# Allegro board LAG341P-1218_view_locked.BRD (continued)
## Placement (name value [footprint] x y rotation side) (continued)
CV1022  -  [C_0603]  236.26 146.37 0 top
CV1023  -  [C_0603]  247.76 147.27 270 top
CV1024  -  [C_0603]  245.22 152.8 180 top
CV1025  -  [C_0603]  247.26 152.99 270 top
CV1026  -  [C_0603]  233.79 160.83 90 top
CV1027  -  [C_0603]  237.5 160.83 90 top
CV1028  -  [C_0603]  235.03 160.83 90 top
CV1029  -  [C_0603]  236.27 160.83 90 top
CV1030  -  [C_0603]  238.72 160.83 90 top
CV1031  -  [C_0402]  247.38 157.17 90 top
CV1032  -  [C_0402]  242.8 157.14 180 top
CV1033  -  [C_0402]  237.24 153.62 180 top
CV1034  -  [C_0402]  247.45 149.67 90 top
CV1035  -  [C_0402]  243.9 151.66 180 top
CV1036  -  [C_0402]  241.17 154.01 180 top
CV1037  -  [C_0402]  246.24 158.88 90 top
CV1038  -  [C_0402]  234.87 157.76 90 top
CV1039  -  [C_0402]  243.73 154.41 180 top
CV1040  -  [C_0402]  237.3 150.77 180 top
CV1041  -  [C_0402]  242.75 125.04 90 top
CV1042  -  [C_0402]  242.62 134.77 0 top
CV1043  -  [C_0402]  236.85 134.51 180 top
CV1044  -  [C_0402]  244.17 130.25 90 top
CV1045  -  [C_0402]  238.75 122.4 270 top
CV1046  -  [C_0402]  235.01 134.53 180 top
CV1047  -  [C_0402]  242.82 124.19 270 top
CV1048  -  [C_0402]  244.27 132.09 90 top
CV1050  -  [C_0402]  212.66 143.78 180 top
CV1051  -  [C_0402]  217.17 146.31 180 top
CZ4  -  [C_0603]  256.84 105.81 180 top
CZ6  -  [C_0603]  256.84 107.08 180 top
CZ8  -  [C_0603]  257.48 103.27 0 top
CZ9  -  [C_0603]  256.1 110.18 0 top
CZ11  -  [C_0603]  52.5 75.08 0 top
CZ12  -  [C_0603]  259.82 107.9 180 top
CZ18  -  [C_0402]  56.95 72.56 270 top
CZ19  -  [C_0402]  60.52 71.61 0 top
CZ20  -  [C_0402]  53.14 69.97 180 top
CZ26  -  [C_0402]  338.56 126.83 0 bottom
CZ28  -  [C_0402]  178.88 147.91 180 top
CZ29  -  [C_0402]  343.33 126.81 90 bottom
CZ31  -  [C_0402]  342.56 129.62 0 bottom
CZ37  -  [C_0603]  233.22 76.28 270 top
CZ39  -  [C_0603]  272.21 73.68 180 top
CZ41  -  [C_0201]  49.49 96.92 180 top
CZ43  -  [C_0402]  49.33 89.86 90 bottom
CZ44  -  [C_0402]  52.37 95.85 270 bottom
CZ45  -  [C_0402]  234.87 76.29 270 top
CZ46  -  [C_0402]  275.51 77.28 90 top
CZ47  -  [C_0402]  178.99 149.37 180 bottom
CZ49  -  [C_0402]  172.25 133.42 90 top
CZ82  -  [C_0402]  183.95 150.82 90 bottom
CZ86  -  [C_0402]  178.99 151.26 90 bottom
CZ88  -  [C_0402]  178.99 150.31 180 bottom
CZ96  -  [C_0402]  179.57 153.1 90 top
CZ97  -  [C_0402]  178.35 154.01 180 top
CZ98  -  [C_0402]  208.98 114.64 180 top
CZ99  -  [C_0402]  208.62 130.65 90 top
CZ100  -  [C_0201]  12.74 129.11 0 bottom
CZ101  -  [C_0201]  13.64 126.26 90 bottom
CZ104  -  [C_0402]  2.59 82.44 180 bottom
CZ105  -  [C_0402]  120.7 81.93 180 top
CZ106  -  [C_0402]  118.07 80.27 90 top
CZ588  -  [C_0402]  104.88 121.68 0 top
CZ1501  -  [C_0402]  124.11 79.64 180 top
CZ2154  -  [C_0603]  242.48 77.01 180 top
CZ2155  -  [C_0402]  239.4 119.78 180 top
CZ2156  -  [C_0402]  127.3 125.32 270 top
CZ2157  -  [C_0201]  56.44 96.96 270 top
D18  -  [ESD101-B1-02ELS_TSSLP-2-4-2]  341.24 126.57 90 bottom
D74  -  [ESD101-B1-02ELS_TSSLP-2-4-2]  341.11 112.1 270 bottom
D123  -  [ESD8011MUT5G_X3DFN2-2]  324.88 137.24 180 bottom
D124  -  [ESD8011MUT5G_X3DFN2-2]  325.91 137.24 0 bottom
D125  -  [AZ5B25-01F_DFN0603P2Y2]  17.61 164.63 270 bottom
D126  -  [AZ5B25-01F_DFN0603P2Y2]  17.61 165.73 90 bottom
D321  -  [RB751S40T1G_SOD523-2]  174.07 70.57 180 top
D322  -  [AZ5125-01HPR7G_SOD523-2]  279.45 75.23 270 top
D323  -  [ESD8011MUT5G_X3DFN2-2]  318.44 103.94 90 bottom
D324  -  [ESD8011MUT5G_X3DFN2-2]  310.31 101.45 270 bottom
DA2  -  [AZ5123-01FPR7G_DFN1006P2X2]  11.27 119.93 0 bottom
DA3  -  [AZ5123-01FPR7G_DFN1006P2X2]  1.29 111.94 180 bottom
DA4  -  [AZ5123-01FPR7G_DFN1006P2X2]  2.08 112.16 270 top
DA5  -  [AZ5123-01FPR7G_DFN1006P2X2]  2.41 125.79 90 bottom
DA7  -  [AZ5125-01HPR7G_SOD523-2]  11.93 110.85 270 top
DA9  -  [AZ5123-01FPR7G_DFN1006P2X2]  12.72 113.21 270 top
DA14  -  [AZ5125-01HPR7G_SOD523-2]  10.72 110.85 270 top
DA56  -  [RB751S40T1G_SOD523-2]  161.76 179.6 0 top
DA57  -  [RB751S40T1G_SOD523-2]  249.52 113.94 0 top
DE4  -  [PESD5V0U2BT_SOT23-3]  197.79 78.1 180 bottom
DE5  -  [PESD5V0U2BT_SOT23-3]  185.19 80.92 270 top
DE7  -  [RB751S40T1G_SOD523-2]  96.8 101.62 0 top
DE8  -  [RB751S40T1G_SOD523-2]  335.48 114.89 180 bottom
DE9  -  [TVNST52302AB0_SOT523-3]  147.37 74.19 0 bottom
DH1  -  [RB751S40T1G_SOD523-2]  82.65 69.17 180 top
DH2  -  [RB751S40T1G_SOD523-2]  60.21 80.22 180 bottom
DI1  -  [RB751S40T1G_SOD523-2]  346.44 113.21 90 bottom
DI3  -  [AZ5125-02SPR7G_SOT23-3]  345.49 109.34 180 bottom
DI7  -  [AZ1045-04F_DFN2510P10E-10-9]  17.38 168.18 90 top
DI9  -  [AZ1045-04F_DFN2510P10E-10-9]  330.32 140.49 270 top
DI12  -  [BAT54CW-7-F_SOT323-3]  326.57 108.42 0 bottom
DI13  -  [ESD108-B1-CSP0201_WLL-2-1-2]  315.06 99.84 0 bottom
DI14  -  [RB751S40T1G_SOD523-2]  305.51 81.55 180 top
DI15  -  [RB751S40T1G_SOD523-2]  246.2 75.9 180 top
DI16  -  [RB751S40T1G_SOD523-2]  244.5 77.17 0 top
DI17  -  [ESD108-B1-CSP0201_WLL-2-1-2]  314.2 99.84 180 bottom
DL1  -  [AZ5125-02SPR7G_SOT23-3]  342.04 182.14 270 top
DN1  -  [RB751S40T1G_SOD523-2]  324.32 148.8 0 bottom
DN2  -  [RB751S40T1G_SOD523-2]  329.62 144.14 90 bottom
DN3  -  [BAT54CW-7-F_SOT323-3]  333.68 110.07 0 bottom
DT10  -  [PESD24VS2UT_SOT23-3]  11.86 137.62 0 bottom
DT12  -  [ESD108-B1-CSP0201_WLL-2-1-2]  8.94 135.97 90 top
DT13  -  [ESD108-B1-CSP0201_WLL-2-1-2]  8.94 135.27 270 top
DT14  -  [ESD108-B1-CSP0201_WLL-2-1-2]  7.7 134.02 0 top
DT15  -  [ESD108-B1-CSP0201_WLL-2-1-2]  8.94 133.75 90 top
DT16  -  [ESD108-B1-CSP0201_WLL-2-1-2]  8.94 133.05 270 top
DT17  -  [ESD108-B1-CSP0201_WLL-2-1-2]  7.74 131.82 0 top
DT18  -  [ESD108-B1-CSP0201_WLL-2-1-2]  8.94 131.06 90 top
DT19  -  [ESD108-B1-CSP0201_WLL-2-1-2]  8.94 130.38 270 top
DT20  -  [ESD108-B1-CSP0201_WLL-2-1-2]  7.16 137.88 90 bottom
DT21  -  [ESD108-B1-CSP0201_WLL-2-1-2]  7.16 137.18 270 bottom
DT22  -  [ESD108-B1-CSP0201_WLL-2-1-2]  2.29 139.21 90 top
DT23  -  [ESD108-B1-CSP0201_WLL-2-1-2]  5.37 140.3 90 top
DT24  -  [ESD108-B1-CSP0201_WLL-2-1-2]  5.38 139.63 270 top
DT25  -  [ESD108-B1-CSP0201_WLL-2-1-2]  5.51 126.76 90 top
DT26  -  [ESD108-B1-CSP0201_WLL-2-1-2]  7.86 129.05 0 bottom
DT27  -  [ESD108-B1-CSP0201_WLL-2-1-2]  7.16 129.05 180 bottom
DT28  -  [RB751S40T1G_SOD523-2]  6.15 133.34 90 bottom
DT29  -  [RB751S40T1G_SOD523-2]  26.7 116.39 0 top
DT174  -  [BZT52C15LP-7_DFN1006-2]  9.38 137.39 90 bottom
DT175  -  [AZ5B25-01F_DFN0603P2Y2]  13.51 155.28 90 top
DT176  -  [AZ5B25-01F_DFN0603P2Y2]  13.51 154.51 270 top
DT177  -  [AZ5B25-01F_DFN0603P2Y2]  12.62 153.63 90 top
DT178  -  [AZ5B25-01F_DFN0603P2Y2]  12.62 152.86 270 top
DT179  -  [AZ5B25-01F_DFN0603P2Y2]  12.62 150.07 90 top
DT180  -  [AZ5B25-01F_DFN0603P2Y2]  12.62 149.31 270 top
DT181  -  [AZ5B25-01F_DFN0603P2Y2]  13.51 151.72 90 top
DT182  -  [AZ5B25-01F_DFN0603P2Y2]  13.51 150.96 270 top
DV1  -  [BAT54CW-7-F_SOT323-3]  45.77 93.93 180 bottom
DV2  -  [BAT54CW-7-F_SOT323-3]  43.23 93.93 180 bottom
DV7  -  [BAT54CW-7-F_SOT323-3]  63.55 95.33 180 top
DV12  -  [IP4220CZ6_SC-74-6]  56.36 96.72 270 bottom
DV13  -  [BAT54CW-7-F_SOT323-3]  206.87 112.86 90 top
DV14  -  [RB751S40T1G_SOD523-2]  211.89 109.59 90 top
DV15  -  [RB751S40T1G_SOD523-2]  213.16 119.3 270 top
DV16  -  [BAT54CW-7-F_SOT323-3]  247.8 110.89 0 top
DZ59  -  [RB751S40T1G_SOD523-2]  126.92 127.99 270 top
FD1  -  [FIDUCIAL_C40M80]  340.98 74.19 0 top
FD2  -  [FIDUCIAL_C40M80]  22.4 176.01 0 top
FD3  -  [FIDUCIAL_C40M80]  21.2 176.87 180 bottom
FD4  -  [FIDUCIAL_C40M80]  340.58 74.19 180 bottom
FD5  -  [FIDUCIAL_C40M80]  219.13 164.74 180 bottom
FD6  -  [FIDUCIAL_C40M80]  130.73 176.68 0 top
H1  -  [H_2P3]  246.16 68.79 0 top
H2  -  [H_2P3]  26.76 172.69 0 top
H5  -  [H_3P9]  245.81 140.69 0 top
H9  -  [H_2P5]  246.46 186.59 0 top
H10  -  [H_2P5]  1.76 71.19 0 top
H11  -  [H_2P1N]  4.91 69.24 0 top
H12  -  [H_6P0N]  6.86 95.89 0 top
H16  -  [H_3P9]  183.55 156.96 0 top
H17  -  [H_2P1X2P5N]  25.37 177.03 346 top
H23  -  [EMIST_SUL-12A2M_1P]  100.56 127.84 270 bottom
H24  -  [EMIST_SUL-12A2M_1P]  100.56 152.94 270 bottom
H25  -  [EMIST_SUL-12A2M_1P]  110.76 121.74 180 bottom
H37  -  [H_3P2]  12.46 69.61 0 top
H38  -  [H_3P2]  2.51 87.83 0 top
H39  -  [H_2P5]  118.76 185.69 0 top
H40  -  [H_2P5]  345.76 70.19 0 top
H41  -  [H_2P8]  206.06 71.71 0 top
H42  -  [H_2P8]  141.46 71.71 0 top
H43  -  [H_2P3]  324.09 143.14 0 top
H45  -  [H_3P9]  183.55 123.52 180 top
H46  -  [H_3P9]  117.36 133.64 0 top
H47  -  [H_6P0N]  340.66 95.89 0 top
H48  -  [H_4P1]  341.76 80.49 0 top
H49  -  [H_2P3]  340.96 187.19 0 top
H50  -  [CLIP_C6-PM]  335.52 184.64 180 bottom
H54  -  [CLIP_C5P5-NPM]  257.35 106.44 180 bottom
H55  -  [CLIP_C5P5-NPM]  73.01 100.58 180 bottom
H59  -  [H_2P9X2P1N]  345.76 73.99 0 top
JAPS  -  [ACES_50506-01841-P01_18P]  176.39 74.63 180 bottom
JAUDIO  -  [ACES_88028-3010M_30P]  1.76 84.34 0 top
JCR  -  [T-SOL_156-1051902601_19P-T]  328.01 123.24 90 top
JDEG1  -  [ACES_50521-01041-P01_10P]  310.78 98.57 180 bottom
JDIMM1  -  [BELLW_SD-80886-1021_260P-T]  105.14 94.54 180 bottom
JDIMM2  -  [BELLW_SD-80886-1021_260P-T]  181.44 94.54 180 bottom
JEDP1  -  [ACES_59003-04006-001_40P]  65.49 103.22 0 bottom
JFAN1  -  [ACES_50224-00401-001_4P]  92.36 102.42 0 bottom
JFAN2  -  [ACES_50224-00401-001_4P]  334.96 121.39 90 bottom
JFP  -  [ACES_50521-00841-P01_8P-T]  315.86 102.28 0 bottom
JHDD  -  [J-L_UCNR2234B020-0_20P]  229.12 77.68 0 bottom
JHDMI1  -  [ACON_HMRB9-AK120C_19P]  9.53 146.62 270 top
JHP1  -  [YUQIU_PJ567-F07J1BE-C_6P]  8.56 123.56 90 top
JKB  -  [E-T_6710K-Y15M-31L_15P]  161.06 77.59 180 bottom
JLPDE1  -  [ACES_50521-01041-P01_10P]  297.32 98.57 180 bottom
JNGFF1  -  [CONCR_213AAAA32FA_67P]  326.32 151.12 0 bottom
JNGFF2  -  [CONCR_213MAAA32FA_67P-T]  258.24 89.74 270 bottom
JRTC  -  [E-T_3806K-F02N-03R_2P]  327.51 171.54 0 top
JSPI1  -  [ACES_50521-01041-P01_10P]  113.33 73.3 180 bottom
JTAG1  -  [SHORTPADS]  300.79 92.73 0 bottom
JTP  -  [ACES_51524-0080N-001_8P]  190.76 77.99 180 bottom
JTS  -  [ACES_50208-00601-P01_6P]  348.12 124.64 90 bottom
JTS1  -  [ACES_50208-00801-003_8P]  343.71 114.95 0 bottom
JUSB1  -  [TAIWI_USB019-107CRL-TWD_10P-T]  12.45 173.89 270 top
JUSB2  -  [TAIWI_USB019-107CRL-TWD_10P-T]  335.08 136.64 90 top
JUSBC1  -  [JAE_DX07S024XJ2_24P-T]  5.62 135.75 270 top
JXDP  -  [SAMTE_BSH-030-01-L-D-A_60P]  125.96 152.7 90 top
LA1  -  [MURAT_BLM15PX600SN1D_2P]  10.1 103.52 0 top
LA2  -  [MURAT_BLM21PG600SN1D_L0805_2P]  12.05 106.58 90 top
LA3  -  [MURAT_BLM15PX600SN1D_2P]  12.88 106.61 270 bottom
LA4  -  [MURAT_BLM15BB220SN1D_2P]  2.3 93.45 0 bottom
LA5  -  [MURAT_BLM15AX700SN1D_2P]  6.61 125.81 180 bottom
LA6  -  [MURAT_BLM15AX700SN1D_2P]  12.13 118.1 90 bottom
LA7  -  [MURAT_BLM15AX700SN1D_2P]  12.73 115.1 270 top
LA8  -  [MURAT_BLM15AX700SN1D_2P]  4.75 112.17 180 top
LED1  -  [LED_LTW-270TLA_2P]  346.76 175.28 270 top
LED2  -  [LED_LTW-270TLA_2P]  346.76 171.68 270 top
LED3  -  [LED_LTW-270TLA_2P]  346.76 168.08 270 top
LED4  -  [LED_LTW-270TLA_2P]  346.76 164.48 270 top
LED5  -  [LED_LTW-270TLA_2P]  346.76 160.88 270 top
LED6  -  [LED_HT-F196BP5_2P]  332.97 186.94 180 top
LH1  -  [MURAT_BLM15PX221SN1D_2P]  89.71 74.08 0 top
LH2  -  [MURAT_BLM15PX221SN1D_2P]  99.45 90.32 90 top
LH3  -  [MURAT_BLM15PX221SN1D_2P]  69.82 91.97 90 bottom
LH4  -  [MURAT_BLM15PX221SN1D_2P]  100.59 89.29 180 bottom
LI1  -  [INPAQ_MCM1012B900F06BP_4P]  341.56 109.5 0 bottom
LI2  -  [INPAQ_MCM1012B900F06BP_4P]  325.86 134.56 90 bottom
LI5  -  [INPAQ_MCM1012B900F06BP_4P]  18.6 167.27 270 bottom
LM1  -  [CHILI_PBY160808T-300Y-N_2P]  24.69 144.05 270 bottom
LM2  -  [CHILI_PBY160808T-300Y-N_2P]  18.72 135.15 90 bottom
LM3  -  [CHILI_PBY160808T-300Y-N_2P]  16.55 143.15 0 bottom
LM4  -  [CHILI_PBY160808T-300Y-N_2P]  22.51 135.37 0 bottom
LM5  -  [CHILI_PBY160808T-300Y-N_2P]  16.04 136.8 0 bottom
LN1  -  [INPAQ_MCM1012B900F06BP_4P]  327.52 147.79 90 bottom
LT1  -  [MAG_MLV-YT10NR68N-M1L_2P]  20.99 115.84 180 bottom
LT12  -  [CHILI_CMMI21T-900Y-N_4P]  11.7 133.2 90 top
LT13  -  [CHILI_CMMI21T-900Y-N_4P]  8.18 139.55 90 top
LT14  -  [CHILI_PBY160808T-300Y-N_2P]  14.61 107.91 90 bottom
LV22  -  [INPAQ_MCM1012B900F06BP_4P]  56.16 92.18 90 bottom
LV23  -  [CHILI_PBY160808T-300Y-N_2P]  196.77 121.48 90 bottom
LV24  -  [KC_FBMA-L11-160808300LMA25T_2P]  189.15 151.92 90 top
MD3  -  [ESD108-B1-CSP0201_WLL-2-1-2]  317.49 100.09 0 bottom
MD4  -  [ESD108-B1-CSP0201_WLL-2-1-2]  319.01 100.09 180 bottom
ML17  -  [CHILI_CMMI21T-900Y-N_4P]  315.05 96.96 180 bottom
NOREF  -  []  198.82 81.55 0 top
NOREF#2  -  []  151.97 98.67 0 top
NOREF#3  -  []  245.81 140.69 0 top
NOREF#4  -  []  206.66 0 0 top
NOREF#5  -  []  183.55 156.96 0 top
NOREF#6  -  []  138.38 24.5 0 top
NOREF#7  -  []  117.36 133.64 0 top
NOREF#8  -  []  183.55 123.52 0 top
NOREF#9  -  []  66.04 137.46 180 bottom
NOREF#10  -  []  216.26 72.9 90 bottom
NOREF#11  -  []  81.25 78.51 180 bottom
NOREF#12  -  []  231.95 102.13 90 bottom
NOREF#13  -  []  204.14 101.62 90 bottom
NOREF#14  -  []  146.22 113.3 180 bottom
PC106  -  [C_0402]  23.71 156.72 0 bottom
PC107  -  [C_0402]  23.67 86.76 90 bottom
PC108  -  [C_0402]  24.56 86.76 90 bottom
PC109  -  [C_0402]  25.12 82.31 0 top
PC110  -  [C_0402]  25.12 83.2 0 top
PC114  -  [C_0402]  25.21 147.69 0 bottom
PC115  -  [C_0402]  25.21 148.71 0 bottom
PC200  -  [C_0402]  22.64 70.47 270 top
PC201  -  [C_0603]  14.15 96.28 180 bottom
PC202  -  [C_0603]  8.31 84.98 180 bottom
PC203  -  [C_0805]  10.97 93.24 90 top
PC204  -  [C_0402]  14.02 101.49 180 bottom
PC205  -  [C_0402]  29.96 70.44 270 top
PC206  -  [C_0402]  29.96 71.39 90 top
PC207  -  [C_0402]  29.33 68.57 0 top
PC208  -  [C_0402]  28.37 92.22 180 top
PC209  -  [C_0402]  26.72 95.01 0 bottom
PC210  -  [C_0402]  19.66 95.01 0 top
PC211  -  [C_0603]  20.82 90.95 180 top
PC212  -  [C_0402]  17.58 87.83 90 top
PC213  -  [C_0402]  22.53 85.24 90 top
PC214  -  [C_0402]  23.8 75.01 270 top
PC215  -  [C_0402]  25.4 76.52 90 top
PC216  -  [C_0402]  22.66 72.28 270 top
PC217  -  [C_0402]  17.63 94.25 0 top
PC218  -  [C_0201]  75.1 96.26 135 top
PC219  -  [C_0402]  59.75 81.43 180 bottom
PC220  -  [C_0603]  64.05 91.88 315 top
PC221  -  [C_0201]  69 89.42 135 top
PC222  -  [C_0402]  67.5 89.62 135 top
PC223  -  [C_0402]  71.12 97.32 315 top
PC335  -  [C_0603]  345.81 92.6 90 top
PC400  -  [C_0603]  345.72 88.11 0 top
PC401  -  [C_0402]  346.65 90.06 180 bottom
PC402  -  [C_0402]  345.67 87.01 0 bottom
PC403  -  [C_0402]  322.54 87.32 90 top
PC404  -  [C_0402]  323.43 87.32 90 top
PC405  -  [C_0402]  321.65 87.32 90 top
PC406  -  [C_0603]  326.49 87.26 90 top
PC407  -  [C_0402]  319.74 87.32 90 top
PC408  -  [C_0402]  320.76 87.32 90 top
PC409  -  [C_0603]  324.76 87.26 90 top
PC410  -  [C_0603]  337.62 91.27 0 top
PC411  -  [C_0603]  342 84.41 0 top
PC412  -  [C_B2]  325.52 93.22 90 top
PC413  -  [C_B2]  321.96 71.34 270 top
PC414  -  [C_0603]  330.63 99.46 180 top
PC415  -  [C_0402]  335.9 88.68 270 top
PC416  -  [C_0402]  330.12 85.67 90 top
PC417  -  [C_0603]  337.21 83.67 90 top
PC418  -  [C_0402]  338.34 88.17 180 top
PC419  -  [C_0603]  338.58 87.03 180 top
PC420  -  [C_D]  321.23 82.95 270 top
PC456  -  [C_B2]  318.76 71.34 270 top
PC500  -  [C_0402]  134.75 75.6 270 top
PC501  -  [C_0402]  134.75 75.6 270 bottom
PC502  -  [C_0201]  128.45 76.4 180 bottom
PC503  -  [C_0603]  136 75.71 0 bottom
PC504  -  [C_0603]  124.32 69.49 180 bottom
PC505  -  [C_0201]  130.1 69.72 0 top
PC506  -  [C_0402]  130.96 69.64 90 bottom
PC507  -  [C_0805]  119.68 71.1 270 bottom
PC508  -  [C_0805]  119.68 71.1 270 top
PC509  -  [C_0805]  121.46 71.1 270 bottom
PC510  -  [C_0805]  121.46 71.1 270 top
PC511  -  [C_0402]  132.46 70.72 270 bottom
PC512  -  [C_0402]  130.01 70.58 270 bottom
PC513  -  [C_0603]  136 75.71 0 top
PC600  -  [C_0603]  282.31 94.57 180 bottom
PC601  -  [C_0603]  273.79 97.3 270 bottom
PC602  -  [C_0603]  274.05 98.09 270 top
PC603  -  [C_0402]  272.72 96.74 270 top
PC604  -  [C_0402]  272.72 96.92 270 bottom
PC605  -  [C_0603]  282.12 97.94 90 top
PC606  -  [C_0603]  279.65 98.04 180 top
PC607  -  [C_0603]  285.1 92.6 0 bottom
PC608  -  [C_D1]  256.02 95.07 90 bottom
PC609  -  [C_0402]  286.05 99.84 180 bottom
PC610  -  [C_0603]  287.9 93.87 270 bottom
PC611  -  [C_0603]  262.56 94.63 270 bottom
PC612  -  [C_0402]  289.48 98.38 90 bottom
PC613  -  [C_0402]  289.6 96.41 0 top
PC614  -  [C_0402]  289.6 97.43 0 bottom
PC615  -  [C_0603]  273.99 99.21 90 bottom
PC700  -  [C_0402]  200.65 183.57 90 top
PC701  -  [C_0402]  194.68 181.84 90 bottom
PC702  -  [C_0603]  199.59 183.18 90 top
PC703  -  [C_0603]  193.56 181.62 90 bottom
PC704  -  [C_0402]  192.79 178.71 180 top
PC705  -  [C_0402]  192.79 179.6 180 top
PC706  -  [C_0402]  189.53 180.56 270 top
PC707  -  [C_0402]  190.49 187.42 270 top
PC708  -  [C_0603]  196.75 182.09 90 top
PC709  -  [C_0402]  204.95 187.34 0 top
PC710  -  [C_0402]  194.68 185.11 90 top
PC711  -  [C_0402]  191.44 186.5 90 top
PC712  -  [C_0402]  185.27 187.47 0 top
PC713  -  [C_0402]  188.34 185.57 180 top
PC714  -  [C_0402]  186.49 184.73 90 top
PC715  -  [C_0402]  212.17 181.86 270 bottom
PC716  -  [C_0402]  211.28 181.86 270 bottom
PC717  -  [C_0805]  213.63 181.93 270 bottom
PC718  -  [C_B2]  212.29 184.15 270 bottom
PC719  -  [C_0805]  208.58 184.84 90 top
PC721  -  [C_0805]  210.93 182.03 270 top
PC722  -  [C_0805]  210.36 184.84 90 top
PC723  -  [C_0603]  214.58 185.4 90 bottom
PC724  -  [C_0603]  211.89 185.5 90 top
PC725  -  [C_0402]  182.68 184.41 180 top
PC800  -  [C_0402]  104.88 131.84 0 bottom
PC801  -  [C_0402]  105.51 135.02 0 top
PC802  -  [C_0603]  104.38 132.99 0 top
PC803  -  [C_0603]  104.38 132.99 0 bottom
PC804  -  [C_0402]  102.03 126.97 270 bottom
PC805  -  [C_0402]  108.76 126.69 90 top
PC806  -  [C_0402]  109.65 130.88 90 bottom
PC807  -  [C_0603]  111.05 126.83 90 bottom
PC808  -  [C_0603]  111.05 126.83 90 top
PC809  -  [C_0603]  112.71 126.83 90 top
PC810  -  [C_0402]  103.56 129.35 90 bottom
PC900  -  [C_0402]  240.08 184.55 90 bottom
PC901  -  [C_0402]  240.97 184.55 90 bottom
PC902  -  [C_0201]  236.14 183.19 270 top
PC903  -  [C_0603]  244.14 183.03 270 bottom
PC904  -  [C_0603]  234.49 181.56 90 top
PC905  -  [C_0402]  236.4 180.03 90 bottom
PC906  -  [C_0402]  239.06 177.74 90 top
PC907  -  [C_0805]  227.25 184.08 90 bottom
PC908  -  [C_0805]  225.54 184.08 90 bottom
PC909  -  [C_0805]  225.56 184.08 90 top
PC910  -  [C_0805]  227.27 184.07 90 top
PC911  -  [C_0402]  242.14 178.66 270 bottom
PC912  -  [C_0402]  238.18 178.66 270 bottom
PC913  -  [C_0603]  242.49 182.9 270 bottom
PC1000  -  [C_0805]  162.85 171.54 90 bottom
PC1001  -  [C_0805]  164.92 169.83 270 top
PC1003  -  [C_0402]  154.33 198.16 180 bottom
PC1004  -  [C_0402]  163.39 169.25 270 top
PC1005  -  [C_0402]  166.55 185.27 90 bottom
PC1006  -  [C_0603]  205.22 138.57 90 top
PC1007  -  [C_0603]  207.19 142.32 90 top
PC1008  -  [C_0603]  209.24 138.6 0 top
PC1009  -  [C_0603]  206.04 144.8 180 top
PC1010  -  [C_0603]  204.01 134.62 270 top
PC1011  -  [C_0603]  204.98 135.6 90 top
PC1012  -  [C_0603]  201.85 144.77 0 top
PC1013  -  [C_0603]  204.44 128.61 0 top
PC1014  -  [C_0603]  201.85 137.88 0 top
PC1015  -  [C_0402]  164.06 181.69 0 top
PC1016  -  [C_0603]  204.56 131.01 0 top
PC1017  -  [C_0402]  165.66 185.27 90 bottom
PC1018  -  [C_0402]  162.45 186.06 180 bottom
PC1019  -  [C_B2]  182.95 161.88 0 bottom
PC1020  -  [C_B2]  188.55 161.84 0 bottom
PC1021  -  [C_B2]  161.01 201.81 90 bottom
PC1022  -  [C_0603]  162.58 176.86 90 bottom
PC1023  -  [C_0603]  201.79 140.1 0 top
PC1024  -  [C_0603]  186.79 194.84 180 top
PC1025  -  [C_0603]  204.33 141.08 0 top
PC1026  -  [C_0603]  204.5 129.81 0 top
PC1027  -  [C_0603]  205.09 142.32 90 top
PC1028  -  [C_0603]  207.31 134.68 270 top
PC1029  -  [C_0603]  208.09 140.89 180 top
PC1030  -  [C_0402]  163.47 176.71 270 bottom
PC1031  -  [C_0402]  211.98 138.16 90 top
PC1032  -  [C_0402]  204.95 132.21 180 top
PC1033  -  [C_0402]  206.6 135.6 0 top
PC1034  -  [C_0402]  201.32 134.66 180 top
PC1035  -  [C_0402]  208.83 133.35 270 top
PC1036  -  [C_0402]  211.96 134.92 0 top
PC1037  -  [C_0402]  210.61 133.35 270 top
PC1038  -  [C_0402]  213.48 141.36 0 top
PC1039  -  [C_0402]  202.54 135.91 0 top
PC1040  -  [C_0402]  211.61 133.35 270 top
PC1041  -  [C_0402]  169.08 186.11 270 bottom
PC1042  -  [C_0805]  163.4 167.16 270 bottom
PC1043  -  [C_0805]  165.35 176.99 0 top
PC1045  -  [C_0402]  154.32 197.25 180 bottom
PC1046  -  [C_0402]  163.65 171.5 180 top
PC1047  -  [C_0603]  167.17 181.64 90 top
PC1048  -  [C_0603]  182.59 164.51 90 top
PC1049  -  [C_0402]  202.55 121.56 180 bottom
PC1050  -  [C_0402]  202.55 122.83 180 bottom
PC1051  -  [C_0603]  183.85 164.5 90 top
PC1052  -  [C_0603]  185.11 164.5 90 top
PC1053  -  [C_0603]  206.17 132.2 0 top
PC1054  -  [C_0402]  168.74 183.96 270 bottom
PC1055  -  [C_0402]  169.68 182.3 0 bottom
PC1056  -  [C_0603]  171.15 183.2 270 top
PC1057  -  [C_0603]  179.31 195.29 180 top
PC1058  -  [C_0603]  182.59 168.47 0 top
PC1059  -  [C_0603]  179.31 191.36 180 top
PC1060  -  [C_0603]  182.59 169.69 0 top
PC1061  -  [C_0603]  179.31 193.96 180 top
PC1062  -  [C_0603]  179.31 192.63 180 top
PC1063  -  [C_0603]  182.59 170.9 0 top
PC1064  -  [C_0603]  179.31 200.49 180 top
PC1065  -  [C_0603]  179.31 201.83 180 top
PC1066  -  [C_0603]  179.31 196.63 180 top
PC1067  -  [C_0603]  179.31 203.09 180 top
PC1068  -  [C_0603]  179.31 204.31 180 top
PC1069  -  [C_0603]  179.31 197.9 180 top
PC1070  -  [C_0603]  179.31 199.2 180 top
PC1100  -  [C_0402]  116.2 167.53 180 top
PC1101  -  [C_0402]  112.9 168.67 180 top
PC1102  -  [C_0402]  109.65 168.24 270 top
PC1103  -  [C_0402]  117.14 168.37 270 top
PC1104  -  [C_0402]  112.88 170.45 0 top
PC1105  -  [C_0402]  112.9 169.56 180 top
PC1106  -  [C_0402]  110.77 173.18 270 bottom
PC1107  -  [C_0402]  112.55 173.18 270 bottom
PC1108  -  [C_0402]  116.2 170.2 180 top
PC1109  -  [C_0402]  115.19 170.74 180 bottom
PC1110  -  [C_0402]  114.27 172.56 270 bottom
PC1111  -  [C_0402]  116.38 172.05 270 top
PC1112  -  [C_0402]  115.48 171.95 90 top
PC1113  -  [C_0402]  105.28 172.74 180 bottom
PC1114  -  [C_0402]  105.28 173.63 180 bottom
PC1115  -  [C_0402]  116.76 174.85 270 top
PC1116  -  [C_0402]  119 172.87 180 top
PC1117  -  [C_0402]  119.68 175.48 270 top
PC1118  -  [C_0402]  104.32 172.03 90 top
PC1119  -  [C_0402]  105.21 174.57 90 top
PC1120  -  [C_0402]  113.64 173.88 0 bottom
PC1121  -  [C_0402]  103.35 175.41 0 top
PC1122  -  [C_0402]  106.53 176.17 0 bottom
PC1123  -  [C_0402]  115.62 178.66 270 top
PC1124  -  [C_0402]  117.4 176.47 90 top
PC1125  -  [C_0402]  116.51 177.39 270 top
PC1126  -  [C_0402]  105.21 177.11 90 top
PC1127  -  [C_0402]  104.32 177.11 90 top
PC1128  -  [C_0402]  106.05 178.96 180 top
PC1129  -  [C_0402]  115.62 180.43 270 top
PC1130  -  [C_0402]  113.59 182.21 270 top
PC1131  -  [C_0402]  106.05 185.18 180 top
PC1132  -  [C_0603]  112.45 181.44 90 top
PC1133  -  [C_0402]  115.62 179.39 90 bottom
PC1134  -  [C_0402]  105.13 179.88 0 top
PC1135  -  [C_0402]  113.26 180.36 0 bottom
PC1136  -  [C_0402]  114.55 178.2 180 bottom
PC1137  -  [C_0402]  105.13 182.64 0 top
PC1202  -  [C_D]  166.24 170.73 90 bottom
PC1203  -  [C_0805]  136.45 184.13 270 bottom
PC1204  -  [C_0805]  134.42 184.13 270 top
PC1205  -  [C_0402]  125.78 180.92 90 top
PC1206  -  [C_0402]  123.75 180.92 90 top
PC1207  -  [C_0402]  124.76 180.92 90 top
PC1208  -  [C_0603]  128.26 186.2 0 bottom
PC1209  -  [C_0402]  135.12 182.38 90 bottom
PC1210  -  [C_0603]  133.08 186.2 0 bottom
PC1211  -  [C_B3]  127.05 176.65 270 top
PC1214  -  [C_B3]  123.75 176.65 270 top
PC1216  -  [C_0603]  129.21 183.47 269.8 top
PC1217  -  [C_0603]  134.04 177.25 90 top
PC1222  -  [C_0402]  144.07 182.38 90 bottom
PC1223  -  [C_0805]  143.56 184.13 270 top
PC1224  -  [C_0805]  136.19 184.13 270 top
PC1225  -  [C_0402]  126.8 180.92 90 top
PC1226  -  [C_0402]  131.75 183.74 270 top
PC1227  -  [C_0603]  140.51 187.41 270 bottom
PC1228  -  [C_0603]  143.05 187.41 270 bottom
PC1229  -  [C_0603]  138.35 183.47 270 top
PC1230  -  [C_0603]  141.66 177.25 90 top
PC1231  -  [C_0805]  145.34 184.13 270 top
PC1232  -  [C_0805]  145.4 184.13 270 bottom
PC1233  -  [C_0402]  140.13 183.86 270 top
PC1234  -  [C_0402]  141.02 183.86 270 top
PC1251  -  [C_0402]  148.7 184.05 270 top
PC1252  -  [C_0402]  153.09 184.05 270 top
PC1254  -  [C_0805]  150.04 184.51 270 top
PC1256  -  [C_0805]  151.75 184.51 270 top
PC1257  -  [C_0603]  148.64 187.28 270 bottom
PC1258  -  [C_0402]  152.96 182.19 90 bottom
PC1259  -  [C_0603]  151.31 187.22 270 bottom
PC1260  -  [C_0603]  147.24 183.47 270 top
PC1261  -  [C_0603]  149.28 177.25 90 top
PC1262  -  [C_0402]  159.75 183.93 270 top
PC1263  -  [C_0402]  160.64 183.93 270 top
PC1264  -  [C_0805]  158.36 184.51 270 top
PC1265  -  [C_0805]  156.64 184.51 270 top
PC1268  -  [C_0603]  156.13 187.28 270 bottom
PC1269  -  [C_0402]  160.45 182.95 90 bottom
PC1270  -  [C_0603]  158.74 187.22 270 bottom
PC1271  -  [C_0603]  154.61 183.34 270 top
PC1272  -  [C_0603]  156.26 177.25 90 top
PC1501  -  [C_0402]  183.14 183.44 180 bottom
PC1502  -  [C_0603]  202.82 134.62 270 top
PC1503  -  [C_0603]  208.84 134.77 0 top
PC1504  -  [C_0402]  201.55 136.48 180 top
PC1505  -  [C_0805]  198.83 194.98 0 bottom
PC1507  -  [C_0603]  209.33 143.21 0 top
PC1508  -  [C_0402]  210.55 136.47 90 top
PC1509  -  [C_0805]  198.83 193.2 0 bottom
PC1510  -  [C_0402]  193.68 174.9 180 top
PC1511  -  [C_0402]  193.68 175.79 180 top
PC1512  -  [C_0603]  206.81 138.07 0 top
PC1513  -  [C_0603]  210.62 141.94 180 top
PC1514  -  [C_0603]  203.31 143.08 180 top
PC1515  -  [C_0402]  206.67 139.49 0 top
PC1516  -  [C_0402]  202.03 141.75 0 top
PC1517  -  [C_0402]  182.01 181.58 270 bottom
PC1518  -  [C_0402]  183.14 182.55 180 bottom
PC1519  -  [C_0603]  189.88 180.29 90 bottom
PC1520  -  [C_0402]  190.3 184.12 270 bottom
PC1521  -  [C_0603]  186.3 171.02 90 top
PC1522  -  [C_0402]  180.49 185.72 0 bottom
PC1523  -  [C_0603]  191.69 169.54 180 top
PC1524  -  [C_0603]  191.69 170.74 180 top
PC1525  -  [C_0603]  191.69 168.29 180 top
PC1526  -  [C_0603]  195.69 171.6 0 top
PC1527  -  [C_0603]  193.98 172.14 90 top
PC1528  -  [C_0603]  191.57 171.91 90 top
PC1529  -  [C_B2]  169.36 196.54 0 bottom
PC1530  -  [C_B2]  192.11 161.87 180 bottom
PC1531  -  [C_0402]  184.1 185.83 0 bottom
PC1532  -  [C_0402]  185.92 185.81 90 bottom
PC1600  -  [C_0402]  242.49 175.53 270 bottom
PC1601  -  [C_0201]  240.06 169.87 180 bottom
PC1602  -  [C_0603]  244.02 175.52 180 top
PC1603  -  [C_0402]  243.85 174.44 180 top
PC1604  -  [C_0603]  239.06 164.29 270 bottom
PC1605  -  [C_0402]  244.73 168.17 180 bottom
PC1606  -  [C_0402]  246.56 168.11 90 bottom
PC1607  -  [C_0603]  245.48 163.49 0 bottom
PC1608  -  [C_0603]  245.48 166.01 0 bottom
PC1609  -  [C_0603]  245.48 164.74 0 bottom
PC1610  -  [C_0603]  245.48 162.27 0 bottom
PC1611  -  [C_0402]  246.61 172.99 0 bottom
PC1612  -  [C_0402]  245.67 168.62 270 bottom
PC1613  -  [C_0603]  243.64 175.9 270 bottom
PC1700  -  [C_0805]  105.5 136.92 0 top
PC1701  -  [C_0402]  103.38 138.07 180 bottom
PC1702  -  [C_0402]  103.38 137.18 180 bottom
PC1703  -  [C_0805]  105.5 138.7 0 top
PC1704  -  [C_0402]  102.46 138.96 0 bottom
PC1705  -  [C_0603]  109.91 134.45 90 bottom
PC1706  -  [C_0603]  107.37 134.45 90 bottom
PC1707  -  [C_0603]  111.49 137.81 0 bottom
PC1708  -  [C_0603]  108.95 143.78 180 top
PC1709  -  [C_0402]  110.41 160.11 270 top
PC1710  -  [C_0402]  111.3 160.11 270 bottom
PC1711  -  [C_0805]  111.81 161.02 270 top
PC1712  -  [C_0805]  109.11 161.31 180 top
PC1713  -  [C_0603]  105.46 165.31 270 bottom
PC1714  -  [C_0402]  110.41 159.2 90 bottom
PC1715  -  [C_0603]  108 165.31 270 bottom
PC1716  -  [C_0603]  102.67 160.99 270 bottom
PC1717  -  [C_0603]  104.64 155.47 0 top
PC1800  -  [C_0402]  176.58 76.98 90 top
PC1801  -  [C_0603]  178.27 77.45 90 bottom
PC1802  -  [C_0402]  178.5 83.29 180 top
PC1803  -  [C_0603]  181.38 81.73 270 top
PC1804  -  [C_0402]  180.95 77.96 90 top
PC1900  -  [C_0603]  52.88 75.33 90 bottom
PC1901  -  [C_0603]  51.61 75.33 90 bottom
PC1902  -  [C_0603]  48.63 69.11 0 top
PC1903  -  [C_0603]  49.07 75.33 90 bottom
PC1904  -  [C_0603]  47.8 75.33 90 bottom
PC1905  -  [C_0603]  48.65 71.64 0 top
PC1906  -  [C_0603]  48.63 70.38 0 top
PC1907  -  [C_0603]  50.34 75.33 90 bottom
PC1908  -  [C_0603]  48.63 68.6 0 bottom
PC1909  -  [C_D]  166.89 166.49 270 bottom
PC1910  -  [C_0402]  46.38 76.9 180 top
PC1911  -  [C_0402]  46.34 76.01 270 top
PC1912  -  [C_0402]  45.45 76.01 270 top
PC1913  -  [C_0603]  41.83 75.39 90 top
PC1914  -  [C_0603]  31.55 94.51 90 bottom
PC1915  -  [C_0603]  32.82 94.51 90 bottom
PC1916  -  [C_0603]  32.82 94.51 90 top
PC1917  -  [C_0603]  34.09 94.51 90 bottom
PC1918  -  [C_0603]  35.36 94.51 90 bottom
PC1919  -  [C_0603]  34.09 94.51 90 top
PC1920  -  [C_0603]  31.55 94.51 90 top
PC1921  -  [C_0603]  30.28 94.51 90 top
PC1922  -  [C_0603]  30.28 94.51 90 bottom
PC1923  -  [C_0402]  41.58 90.9 270 bottom
PC1924  -  [C_0402]  41.58 88.21 90 bottom
PC1925  -  [C_0402]  51.28 80.23 270 bottom
PC1926  -  [C_0603]  50.22 78.89 90 top
PC1927  -  [C_0402]  39.47 76.85 0 top
PC1928  -  [C_0402]  51.73 81.55 0 top
PC1929  -  [C_0603]  41.26 79.14 180 top
PC1930  -  [C_0603]  24.77 90.37 270 bottom
PC1931  -  [C_0603]  26.21 92.6 0 bottom
PC1932  -  [C_0402]  29.13 83.79 270 bottom
PC1933  -  [C_0402]  40.44 86.12 180 top
PC1934  -  [C_0402]  50.52 86.44 0 top
PC1935  -  [C_0402]  40.13 81.55 180 top
PC1936  -  [C_0402]  36.25 73.42 0 top
PC1937  -  [C_0402]  31.1 79.72 270 top
PC1938  -  [C_0402]  40.13 82.57 180 top
PC1939  -  [C_0402]  45.59 87.25 90 top
PC1940  -  [C_0402]  43.04 87.19 90 top
PC1941  -  [C_0402]  46.52 87.25 90 top
PC1942  -  [C_0402]  41.07 84.3 270 top
PC1943  -  [C_0402]  40.13 85.11 180 top
PC1944  -  [C_0402]  60.45 83.14 180 top
PC1945  -  [C_0402]  39.54 87.08 0 top
PC2000  -  [C_0603]  180.01 192.13 90 bottom
PC2001  -  [C_D2E]  149.94 165.12 180 bottom
PC2002  -  [C_D2E]  154.33 165.12 0 bottom
PC2003  -  [C_0603]  145.72 171.66 90 top
PC2004  -  [C_0201]  153.98 139.92 0 top
PC2005  -  [C_0201]  160.5 153.57 0 top
PC2006  -  [C_0201]  152.62 145.56 180 top
PC2007  -  [C_0201]  158.95 136.31 180 top
PC2008  -  [C_0201]  165.52 136.28 0 top
PC2009  -  [C_0201]  153.05 147.88 180 top
PC2010  -  [C_0603]  156.95 155.2 270 top
PC2011  -  [C_EEFSS0D221R]  159.17 143.92 0 top
PC2012  -  [C_0603]  159.01 147.15 180 top
PC2013  -  [C_0603]  154.77 151.48 0 top
PC2014  -  [C_0603]  155.05 140.9 0 top
PC2015  -  [C_0603]  158.56 149.65 180 top
PC2016  -  [C_0603]  163.93 147.18 180 top
PC2017  -  [C_0603]  164.36 137.88 180 top
PC2018  -  [C_0603]  159.54 137.88 180 top
PC2019  -  [C_D2E]  198.11 169.01 270 bottom
PC2020  -  [C_B2]  119.56 145.03 90 bottom
PC2021  -  [C_0603]  143.58 137.32 180 top
PC2022  -  [C_0603]  119.81 142.32 270 top
PC2023  -  [C_0603]  144.47 144.93 0 top
PC2024  -  [C_0603]  143.52 144.89 180 top
PC2025  -  [C_0603]  149.47 146.52 0 top
PC2026  -  [C_0603]  149.45 147.77 0 top
PC2027  -  [C_0603]  149.18 143.26 0 top
PC2028  -  [C_EEFSS0D221R]  149.94 166.13 180 top
PC2029  -  [C_0201]  155.69 152.44 0 top
PC2030  -  [C_0201]  160.57 148.07 0 top
PC2031  -  [C_0201]  153.99 138.7 0 top
PC2032  -  [C_0201]  160.85 136.94 0 top
PC2033  -  [C_0201]  165.56 136.91 0 top
PC2034  -  [C_0201]  153.97 138.12 0 top
PC2035  -  [C_0201]  163.72 136.92 180 top
PC2036  -  [C_0201]  158.92 136.98 180 top
PC2037  -  [C_0201]  163.5 148.07 180 top
PC2038  -  [C_0201]  159.04 150.61 180 top
PC2039  -  [C_0603]  159.4 140.82 180 top
PC2040  -  [C_0603]  160.13 164.36 0 top
PC2041  -  [C_0603]  156.36 144.38 90 top
PC2042  -  [C_0201]  160.52 153 0 top
PC2043  -  [C_0201]  165.62 154.7 0 top
PC2044  -  [C_0201]  153.98 136.23 0 top
PC2045  -  [C_0201]  155.69 153.69 180 top
PC2046  -  [C_0201]  155.35 148.18 0 top
PC2047  -  [C_0201]  165.46 151.6 0 top
PC2048  -  [C_0201]  163.69 150.89 180 top
PC2049  -  [C_0201]  163.33 151.79 180 top
PC2050  -  [C_0201]  152.62 138.45 180 top
PC2051  -  [C_0201]  159.69 150.5 0 top
PC2052  -  [C_0201]  155.69 153.03 0 top
PC2053  -  [C_0201]  158.68 148.66 180 top
PC2054  -  [C_0201]  165.47 150.89 0 top
PC2055  -  [C_0201]  160.49 151.78 0 top
PC2056  -  [C_0201]  153.98 139.33 0 top
PC2057  -  [C_0201]  165.37 152.42 0 top
PC2058  -  [C_0201]  165.37 153.56 0 top
PC2059  -  [C_0201]  163.32 152.94 180 top
PC2060  -  [C_0201]  163.33 153.54 180 top
PC2061  -  [C_0201]  165.62 155.34 0 top
PC2062  -  [C_0201]  158.7 148.07 180 top
PC2063  -  [C_0201]  165.37 148.07 0 top
PC2064  -  [C_0201]  160.5 152.39 0 top
PC2065  -  [C_0201]  154.02 137.47 0 top
PC2066  -  [C_0201]  159.68 151.08 0 top
PC2067  -  [C_0201]  163.73 136.28 180 top
PC2068  -  [C_0201]  152.62 140.29 180 top
PC2069  -  [C_0201]  152.62 144.16 180 top
PC2070  -  [C_0201]  154 136.85 0 top
PC2071  -  [C_0201]  160.84 136.36 0 top
PC2072  -  [C_0201]  163.34 152.36 180 top
PC2073  -  [C_0201]  165.37 152.99 0 top
PC2074  -  [C_0201]  149.84 152.51 0 top
PC2075  -  [C_0201]  143.09 136.42 180 top
PC2076  -  [C_0201]  149.78 136.43 0 top
PC2077  -  [C_0201]  149.77 151.2 0 top
PC2078  -  [C_0201]  149.71 149.95 0 top
PC2079  -  [C_0201]  149.35 154.56 0 top
PC2080  -  [C_0201]  143.01 135.43 270 top
PC2081  -  [C_0201]  143.95 135.37 270 top
PC2082  -  [C_0201]  150.98 136.43 0 top
PC2083  -  [C_0201]  141.91 135.82 90 top
PC2084  -  [C_0201]  144.82 135.39 270 top
PC2085  -  [C_0201]  150.72 135.6 0 top
PC2086  -  [C_0603]  160.13 165.56 0 top
PC2087  -  [C_0603]  155.15 143.37 270 top
PC2088  -  [C_0603]  160.13 166.77 0 top
PC2089  -  [C_0603]  160.16 149.61 0 top
PC2090  -  [C_0603]  146.99 171.66 90 top
PC2091  -  [C_0603]  144.64 146.52 0 top
PC2092  -  [C_0603]  144.35 143.24 0 top
PC2093  -  [C_0603]  149.55 140.26 0 top
PC2094  -  [C_0603]  144.62 147.77 0 top
PC2095  -  [C_0603]  152.7 171.66 90 top
PC2096  -  [C_0603]  160.12 147.18 0 top
PC2097  -  [C_0603]  165.38 137.88 0 top
PC2098  -  [C_0603]  164.95 147.18 0 top
PC2099  -  [C_0603]  151.43 171.66 90 top
PC2100  -  [C_0603]  160.13 167.98 0 top
PC2101  -  [C_0603]  160.55 137.88 0 top
PC2102  -  [C_0603]  144.45 171.67 90 top
PC2103  -  [C_0603]  164.92 149.6 0 top
PC2104  -  [C_0603]  165.37 139.13 0 top
PC2105  -  [C_0603]  163.95 149.59 180 top
PC2106  -  [C_0603]  160.55 139.11 0 top
PC2107  -  [C_0603]  159.6 139.12 180 top
PC2108  -  [C_0603]  165.18 140.77 0 top
PC2109  -  [C_0603]  164.23 140.82 180 top
PC2110  -  [C_0603]  160.42 140.82 0 top
PC2111  -  [C_0603]  164.35 139.11 180 top
PC2112  -  [C_0603]  156.42 143.37 270 top
PC2113  -  [C_0603]  154.79 147.25 0 top
PC2114  -  [C_0603]  136.45 171.66 90 top
PC2115  -  [C_0603]  154.8 149.67 0 top
PC2116  -  [C_0603]  152.9 141.88 180 top
PC2117  -  [C_0603]  155.09 144.38 90 top
PC2118  -  [C_0603]  116.51 142.32 270 top
PC2119  -  [C_0603]  115.24 142.32 270 top
PC2120  -  [C_0603]  113.97 142.32 270 top
PC2121  -  [C_0603]  148.53 137.32 180 top
PC2122  -  [C_0603]  144.72 137.32 0 top
PC2123  -  [C_0603]  149.23 144.91 0 top
PC2124  -  [C_0603]  148.22 144.91 180 top
PC2125  -  [C_0603]  149.55 137.32 0 top
PC2126  -  [C_0603]  149.51 138.99 0 top
PC2127  -  [C_0603]  148.5 138.99 180 top
PC2128  -  [C_0603]  144.69 138.99 0 top
PC2129  -  [C_0603]  143.54 138.99 180 top
PC2130  -  [C_0603]  148.4 140.26 180 top
PC2131  -  [C_0603]  148.45 146.52 180 top
PC2132  -  [C_0603]  148.43 147.77 180 top
PC2133  -  [C_0603]  148.17 143.26 180 top
PC2134  -  [C_0603]  144.59 140.26 0 top
PC2135  -  [C_0603]  143.45 140.26 180 top
PC2136  -  [C_0603]  143.33 143.24 180 top
PC2137  -  [C_0603]  143.62 146.52 180 top
PC2138  -  [C_0603]  143.61 147.77 180 top
PC2139  -  [C_0603]  169.34 142.84 180 top
PC2140  -  [C_0603]  169.34 141.62 180 top
PC2141  -  [C_0603]  169.34 144.04 180 top
PC2142  -  [C_0603]  169.34 145.31 180 top
PC2143  -  [C_0603]  169.43 140.38 180 top
PC2144  -  [C_0603]  117.02 155.28 90 top
PC2145  -  [C_0603]  115.75 155.28 90 top
PC2146  -  [C_0603]  114.48 155.28 90 bottom
PC2147  -  [C_0603]  117.02 155.28 90 bottom
PC2148  -  [C_0603]  115.75 155.28 90 bottom
PC2149  -  [C_0603]  114.48 155.28 90 top
PC2150  -  [C_0603]  173.69 159.02 90 bottom
PC2151  -  [C_0603]  176.25 192.13 90 bottom
PC2152  -  [C_0603]  177.52 192.13 90 bottom
PC2153  -  [C_0603]  178.79 192.13 90 bottom
PD100  -  [AZ5125-01HPR7G_SOD523-2]  26.09 148.75 90 top
PD101  -  [TVNST52302AB0_SOT523-3]  11.86 76.92 0 top
PD102  -  [TVNST52302AB0_SOT523-3]  19.1 69.8 180 top
PD200  -  [PDS1040-13_POWERDI5-3]  13 86.76 90 bottom
PD201  -  [PDS1040-13_POWERDI5-3]  18.01 86.76 90 bottom
PD202  -  [RB751V-40_SOD323-2]  19.54 77.36 180 top
PD203  -  [RB520SM-30T2R_EMD2-2]  64.73 89.23 225 top
PD204  -  [RB520SM-30T2R_EMD2-2]  62.59 92.03 225 top
PD1900  -  [RB751V-40_SOD323-2]  55.42 82.62 270 top
PD1902  -  [RB751V-40_SOD323-2]  57.55 82.62 270 top
PD1903  -  [BAT54CW_SOT323-3]  60.26 78.68 0 top
PD1904  -  [SMF22A-SOD123FL-2-S]  55.78 73.29 270 bottom
PH1100  -  [R_0402]  103.63 150.89 180 bottom
PH1101  -  [R_0402]  131.11 173.68 90 bottom
PH1102  -  [R_0402]  110.59 151.4 0 bottom
PH1103  -  [R_0402]  127.94 180.54 90 bottom
PH1104  -  [R_0402]  106.35 134.94 90 bottom
PJP200  -  [JUMP_43X118]  23.63 94.62 180 top
PJP400  -  [JUMP_43X118]  316.34 78 0 top
PJP402  -  [JUMP_43X118]  322.47 92.02 180 top
PJP403  -  [JUMP_43X118]  315.78 72.41 180 top
PJP500  -  [JUMP_43X118]  118.59 73.73 90 bottom
PJP600  -  [JUMP_43X118]  277.35 97.97 180 bottom
PJP601  -  [JUMP_43X39]  280.91 97.62 0 bottom
PJP602  -  [JUMP_43X79]  280.78 96.09 270 top
PJP603  -  [JUMP_43X118]  254.5 92.39 270 bottom
PJP701  -  [JUMP_43X118]  216.7 184.83 0 bottom
PJP702  -  [JUMP_43X118]  214 184.93 0 top
PJP801  -  [JUMP_43X118]  113.04 125.37 0 bottom
PJP900  -  [JUMP_43X39]  222.4 182.9 0 bottom
PJP1302  -  [JUMP_43X79]  112.98 78.58 180 bottom
PJP1303  -  [JUMP_43X79]  116.26 79.22 90 bottom
PJP1600  -  [JUMP_43X118]  242.37 164.02 270 bottom
PJP1604  -  [JUMP_43X79]  161.85 117.92 270 top
PL104  -  [MURAT_BLM15AG102SN1D_2P]  24.16 149.13 90 top
PL105  -  [TAI-T_HCB2012KF-121T50_2P]  23.83 153.51 0 bottom
PL106  -  [TAI-T_HCB2012KF-121T50_2P]  23.83 155.33 0 bottom
PL107  -  [TAI-T_HCB2012KF-121T50_2P]  27.76 83.36 180 bottom
PL108  -  [TAI-T_HCB2012KF-121T50_2P]  24.31 85.67 270 bottom
PL200  -  [TAI-T_HCB2012KF-121T50_2P]  28.63 94.63 180 top
PL201  -  [TAI-T_HCB2012KF-121T50_2P]  28.63 96.41 180 top
PL400  -  [CYNTE_PCMB063T-3R3MS_2P]  329.07 95.21 0 top
PL401  -  [CYNTE_PCMB103T-2R2MS_2P]  335.58 74.14 180 top
PL402  -  [TAI-T_HCB2012KF-121T50_2P]  316.09 81.62 0 top
PL403  -  [TAI-T_HCB2012KF-121T50_2P]  316.09 83.4 0 top
PL500  -  [TAI-T_HCB2012KF-121T50_2P]  136.32 79.01 270 bottom
PL501  -  [CYNTE_PCMB053T-1R0MS_2P]  127.45 73.18 180 bottom
PL600  -  [CYNTE_PCMB063T-1R0MS_2P]  260.3 98.95 0 bottom
PL601  -  [TAI-T_HCB2012KF-121T50_2P]  277.35 94.43 180 bottom
PL700  -  [L_7X7X3_M_2P]  202.41 182.92 0 bottom
PL777  -  [TAI-T_HCB2012KF-121T50_2P]  194.49 179.94 270 top
PL800  -  [CYNTE_PCMB053T-1R0MS_2P]  104.05 125.24 0 bottom
PL801  -  [TAI-T_HCB2012KF-121T50_2P]  102.7 134.64 0 top
PL900  -  [TAI-T_HCB2012KF-121T50_2P]  245.67 180.1 90 bottom
PL901  -  [CYNTE_PCMB053T-1R0MS_2P]  233.38 181.66 180 bottom
PL1000  -  [TAI-T_HCB2012KF-121T50_2P]  162 173.47 0 top
PL1001  -  [TAI-T_HCB2012KF-121T50_2P]  162.01 175.28 0 top
PL1002  -  [MAG_MMD-06DZIR22MEM2L_2P]  177.44 167.06 0 bottom
PL1003  -  [MAG_MMD-06DZIR22MEM2L_2P]  178.04 174.12 0 bottom
PL1200  -  [TAI-T_HCB2012KF-121T50_2P]  127.18 174.17 90 bottom
PL1201  -  [TAI-T_HCB2012KF-121T50_2P]  125.27 174.17 90 bottom
PL1202  -  [L_7X7X4_M]  135.31 177.29 270 bottom
PL1203  -  [L_7X7X4_M]  142.93 176.91 270 bottom
PL1204  -  [TAI-T_HCB2012KF-121T50_2P]  123.37 174.17 90 bottom
PL1251  -  [L_7X7X4_M]  150.55 176.91 270 bottom
PL1252  -  [L_7X7X4_M]  158.17 176.91 270 bottom
PL1500  -  [MAG_MMD-06DZIR22MEM2L_2P]  187.7 167.02 0 bottom
PL1501  -  [TAI-T_HCB2012KF-121T50_2P]  195 177.02 270 top
PL1502  -  [TAI-T_HCB2012KF-121T50_2P]  196.77 177.02 270 top
PL1600  -  [TAI-T_HCB2012KF-121T50_2P]  245.36 178.86 270 bottom
PL1601  -  [L_2P5X2X1P2_F_2P]  241.99 168.08 270 bottom
PL1700  -  [TAI-T_HCB2012KF-121T50_2P]  104.95 134.42 90 bottom
PL1701  -  [TAI-T_HCB2012KF-121T50_2P]  103.05 134.42 90 bottom
PL1702  -  [L_7X7X4_M]  104.98 146.96 0 bottom
PL1703  -  [TAI-T_HCB2012KF-121T50_2P]  112.15 161.69 180 bottom
PL1704  -  [MAG_MMD05CZR47M_4P]  105.06 153.94 0 bottom
PL1900  -  [MAGLA_MMD-05CZ-1R0M-M7L_2P]  48.9 72.09 0 bottom
PL1901  -  [MAG_MMD-10DZ-1R0M-X1A_2P]  34.09 71.47 90 bottom
PQ100  -  [FDV301N-G_SOT23-3]  21.26 149.47 0 top
PQ101  -  [MMBT3904WH_SOT323-3]  22.28 154.41 180 top
PQ200  -  [FDMC6679AZ_MLP8-5]  12.04 95.14 0 bottom
PQ201  -  [FDMC6679AZ_MLP8-5]  9.17 87.01 180 bottom
PQ202  -  [AO3409_SOT23-3]  7.67 88.9 180 top
PQ203  -  [DMN65D8LDW-7_SOT363-6]  13.27 89.79 90 top
PQ204  -  [DMN65D8LW-7_SOT323-3]  6.82 91.44 90 top
PQ205  -  [DMN65D8LW-7_SOT323-3]  12.06 98.41 0 bottom
PQ206  -  [DMN65D8LW-7_SOT323-3]  14.72 96.41 270 top
PQ207  -  [FDMC6679AZ_MLP8-5]  21.89 93.36 90 bottom
PQ208  -  [FDMC6679AZ_MLP8-5]  18.95 95.14 270 bottom
PQ209  -  [FDMC6679AZ_MLP8-5]  23.16 88.92 180 bottom
PQ210  -  [AO3409_SOT23-3]  25.07 88.66 0 top
PQ211  -  [AO3409_SOT23-3]  15.06 88.82 180 top
PQ212  -  [DMN65D8LDW-7_SOT363-6]  27.72 87.33 0 top
PQ213  -  [DMN65D8LDW-7_SOT363-6]  15.4 90.71 0 top
PQ214  -  [DMN65D8LDW-7_SOT363-6]  17.05 82.63 0 top
PQ215  -  [DMN65D8LDW-7_SOT363-6]  15.99 96.68 270 top
PQ216  -  [DMN65D8LDW-7_SOT363-6]  18.1 80.6 180 top
PQ217  -  [DMN65D8LW-7_SOT323-3]  20.75 81.13 0 top
PQ219  -  [2N7002KDW_SOT363-6]  75.82 99.66 315 top
PQ220  -  [DMN66D0LDW-7_SOT363-6]  57.15 83.94 270 bottom
PQ221  -  [DMN66D0LDW-7_SOT363-6]  55.58 79.88 90 bottom
PQ222  -  [SI1303DL-T1-E3_SOT323-3]  71.86 93.54 315 top
PQ223  -  [DMN66D0LDW-7_SOT363-6]  56.53 87.7 270 bottom
PQ224  -  [DMN65D8LW-7_SOT323-3]  60.48 83.03 270 bottom
PQ225  -  [DMN65D8LW-7_SOT323-3]  69 91.48 135 top
PQ226  -  [SI1303DL-T1-E3_SOT323-3]  73.01 100.38 135 top
PQ227  -  [DMN66D0LDW-7_SOT363-6]  52.28 83.86 270 bottom
PQ400  -  [AON7408L_DFN8-5]  330.19 90.76 180 top
PQ401  -  [AON6380_DFN5X6-8-5]  324.73 80.2 0 top
PQ402  -  [AON7506_DFN3X3-8-5]  332.35 87.71 0 top
PQ403  -  [AON6796_DFN5X6-8-5]  335.52 85.67 180 top
PQ600  -  [AON7406L_DFN8-5]  269.25 98.21 90 bottom
PQ601  -  [AON7534_DFN3X3-8-5]  271.11 95.37 270 bottom
PQ700  -  [AON6962_DFN5X6D-8-7]  199.78 180.3 180 bottom
PQ701  -  [2N7002DW-7-F_SOT363-6]  182.15 185.36 0 top
PQ1000  -  [Q_N_DFN56-8-5]  174.35 164.73 180 bottom
PQ1001  -  [Q_N_DFN56-8-5]  167.4 174.97 270 top
PQ1002  -  [Q_N_DFN56-8-5]  175.02 177.26 270 bottom
PQ1003  -  [Q_N_DFN56-8-5]  174.99 185.53 0 bottom
PQ1007  -  [Q_N_DFN56-8-5]  167.43 168.8 270 top
PQ1008  -  [Q_N_DFN56-8-5]  178.78 185.24 180 top
PQ1500  -  [Q_N_DFN56-8-5]  193.74 173.04 90 bottom
PQ1501  -  [Q_N_DFN56-8-5]  187.57 177.05 0 bottom
PQ1900  -  [AON6380_DFN5X6-8-5]  40.57 72.66 270 top
PQ1901  -  [AON6232A_DFN5X6-8-5]  39.8 85.3 180 bottom
PQ1902  -  [AON6380_DFN5X6-8-5]  40.63 69.42 90 bottom
PQ1903  -  [AON6232A_DFN5X6-8-5]  45.84 79.56 270 bottom
PQ1904  -  [AON6380_DFN5X6-8-5]  47.54 85.62 270 bottom
PQ1905  -  [AON7405_DFN8-5]  26.19 88.07 0 bottom
PQ1906  -  [DMN65D8LW-7_SOT323-3]  54.53 87.9 180 top
PR100  -  [R_0402]  21.34 153.18 180 top
PR101  -  [R_0402]  18.9 154.7 0 top
PR102  -  [R_0402]  25.04 150.02 270 top
PR103  -  [R_0402]  21.34 153.94 180 top
PR104  -  [R_0402]  22.2 153.18 0 top
PR105  -  [R_0402]  20.62 154.75 90 top
PR106  -  [R_0402]  12.62 73.5 180 top
PR108  -  [R_0402]  12.62 74.26 180 top
PR111  -  [R_0402]  17.45 72.74 270 top
PR112  -  [R_0402]  17.65 71.01 180 top
PR200  -  [R_0402]  11.35 86.63 90 top
PR201  -  [R_0402]  8.05 86 180 bottom
PR202  -  [R_0402]  13 97.3 0 bottom
PR203  -  [R_0402]  12.24 93.74 90 top
PR204  -  [R_0402]  12.24 87.52 90 top
PR205  -  [R_0402]  5.64 90.95 90 top
PR206  -  [R_0402]  13.13 92.98 270 top
PR207  -  [R_0402]  31.7 71.25 0 top
PR208  -  [R_0402]  27.49 68.29 0 top
PR209  -  [R_0402]  13.89 98.06 180 bottom
PR210  -  [R0402_0OHM]  14.15 90.49 90 top
PR211  -  [R_0402]  32.62 70.4 180 top
PR212  -  [R_0402]  32.55 69.61 180 top
PR213  -  [R0402_0OHM]  10.07 88.96 90 top
PR214  -  [R0402_0OHM]  14.78 97.25 90 bottom
PR215  -  [R0402_0OHM]  15.54 97.25 90 bottom
PR216  -  [R0402_0OHM]  10.32 97.89 90 bottom
PR217  -  [R_0402]  10.08 91.38 90 top
PR218  -  [R0402_0OHM]  12.37 92.07 90 top
PR219  -  [R_0402]  30.85 71.39 90 top
PR220  -  [R_0402]  30.86 70.48 270 top
PR221  -  [R0402_0OHM]  16.76 98.19 180 top
PR222  -  [R_0402]  15.11 98.19 180 top
PR223  -  [R0402_0OHM]  12.55 98.19 0 top
PR224  -  [R_0402]  15.6 96.41 0 bottom
PR225  -  [R_0402]  25.32 92.47 0 top
PR226  -  [R_0402]  17.42 86.71 270 top
PR227  -  [R_0402]  26.72 94.13 0 bottom
PR228  -  [R_0402]  20.57 94.13 180 top
PR229  -  [R_0402]  20.57 91.97 180 top
PR230  -  [R_0402]  18.47 87.83 90 top
PR231  -  [R_0402]  27.15 86.38 0 top
PR232  -  [R_0402]  27.41 90.21 0 top
PR233  -  [R_0402]  18.19 86.48 270 top
PR234  -  [R_0402]  26.33 74.11 90 top
PR235  -  [R_0402]  16.48 89.81 0 top
PR236  -  [R_0402]  19.23 86.33 270 top
PR237  -  [R_0402]  16.76 93.49 180 top
PR238  -  [R0402_0OHM]  19.35 82.36 90 top
PR239  -  [R0402_0OHM]  14.15 93.11 270 top
PR240  -  [R_0402]  19.69 96.54 180 top
PR241  -  [R_0402]  14.2 93.87 0 top
PR242  -  [R0402_0OHM]  17.83 91.66 270 top
PR243  -  [R0402_0OHM]  19.23 87.06 90 top
PR244  -  [R_0402]  27.36 77.51 270 top
PR245  -  [R_0402]  22.9 75.01 270 top
PR246  -  [R_0402]  15.11 94.76 180 top
PR247  -  [R_0402]  23.29 80.71 90 top
PR248  -  [R_0402]  22.53 80.71 90 top
PR249  -  [R_0402]  25.44 74.13 90 top
PR250  -  [R0402_0OHM]  20.24 82.36 90 top
PR251  -  [R_0402]  20.62 72.28 0 top
PR252  -  [R0402_0OHM]  21.13 82.36 90 top
PR253  -  [R0402_0OHM]  15.85 94.25 0 top
PR254  -  [R_0402]  24.68 75.02 270 top
PR255  -  [R_0402]  26.36 76.54 90 top
PR256  -  [R0402_0OHM]  23.37 79.9 180 top
PR257  -  [R_0402]  22.45 79.14 0 top
PR258  -  [R0402_0OHM]  22.45 78.38 0 top
PR259  -  [R_0402]  22.02 83.28 270 top
PR260  -  [R0402_0OHM]  20.8 77.87 0 top
PR261  -  [R_0402]  18.06 81.5 180 top
PR262  -  [R0402_0OHM]  18.93 81.51 0 top
PR263  -  [R_0402]  76.61 96.58 45 top
PR265  -  [R_0402]  54.28 82.44 270 bottom
PR266  -  [R0805_0OHM]  73.77 97.61 45 top
PR267  -  [R_0402]  54.6 80.73 180 bottom
PR268  -  [R0402_0OHM]  53.64 79.9 0 bottom
PR269  -  [R0402_0OHM]  54.15 84.09 270 bottom
PR270  -  [R_0402]  59.42 82.43 90 bottom
PR271  -  [R_0201]  69.92 89.39 225 top
PR272  -  [R0402_0OHM]  58.15 82.43 90 bottom
PR273  -  [R_0402]  54.52 88.66 0 bottom
PR274  -  [R_0402]  57.45 86.76 0 bottom
PR275  -  [R_0201]  71.4 98.18 315 top
PR276  -  [R_0402]  70.67 93.95 135 top
PR277  -  [R_0402]  52.84 87.02 0 bottom
PR278  -  [R0402_0OHM]  52.84 86.23 0 bottom
PR279  -  [R_0402]  51.63 84.81 90 bottom
PR280  -  [R_0402]  66.9 88.98 135 top
PR282  -  [R_0402]  51.49 81.55 0 bottom
PR283  -  [R_0402]  53.33 87.82 90 bottom
PR284  -  [R0402_0OHM]  49.96 85.74 270 bottom
PR285  -  [R_0402]  50.85 85.74 270 bottom
PR288  -  [R_0201]  74.7 95.86 135 top
PR289  -  [R0805_0OHM]  69.61 96.98 315 top
PR290  -  [R_0201]  70.87 100.89 45 top
PR295  -  [R_0201]  69.08 90.24 315 top
PR326  -  [R_0402]  344.73 93.49 270 top
PR400  -  [R0402_0OHM]  346.65 89.17 180 bottom
PR401  -  [R_0402]  346.63 90.06 180 top
PR402  -  [R_0402]  345.8 86.12 0 top
PR403  -  [R_0402]  346.63 89.17 180 top
PR404  -  [R_0402]  345.8 87.01 0 top
PR405  -  [R_0402]  344.73 91.6 270 top
PR406  -  [R_0402]  345.8 85.24 0 top
PR407  -  [R0402_0OHM]  342.89 91.6 270 top
PR408  -  [R0402_0OHM]  343.84 91.6 270 top
PR409  -  [R0402_0OHM]  345.74 84.33 90 bottom
PR410  -  [R_0402]  345.8 84.28 0 top
PR411  -  [R_0603]  340.03 91.27 0 top
PR412  -  [R_0603]  339.65 84.41 0 top
PR413  -  [R_1206]  334.7 99.71 180 top
PR414  -  [R_1206]  337.59 79.61 90 top
PR415  -  [R0402_0OHM]  338.34 89.16 180 top
PR428  -  [R_0402]  342.89 91.6 270 bottom
PR500  -  [R_0402]  135.32 71.14 180 bottom
PR501  -  [R0402_0OHM]  130.1 76.4 180 bottom
PR502  -  [R_1206]  128.13 69.49 180 bottom
PR503  -  [R_0402]  133.35 69.86 90 bottom
PR504  -  [R_0402]  130.86 68.27 0 bottom
PR505  -  [R_0201]  133.15 72.15 90 top
PR506  -  [R_0201]  130.57 72.28 0 top
PR507  -  [R_0402]  132.56 68.28 0 bottom
PR508  -  [R_0201]  132.6 70.76 0 top
PR521  -  [R0402_0OHM]  134.42 70.38 0 bottom
PR600  -  [R_0603]  280.91 95.84 0 bottom
PR601  -  [R_0402]  286.75 93.68 180 bottom
PR602  -  [R_1206]  266.56 94.06 180 bottom
PR603  -  [R_0603]  287.28 92.46 90 top
PR604  -  [R_0402]  289.61 98.32 90 top
PR605  -  [R_0402]  289.99 93.64 180 bottom
PR606  -  [R0402_0OHM]  289.6 94.75 90 bottom
PR607  -  [R_0402]  290.37 98.32 90 bottom
PR608  -  [R0402_0OHM]  290.51 96.54 180 bottom
PR609  -  [R_0402]  289.56 94.57 180 top
PR610  -  [R_0402]  287.73 97.77 90 top
PR651  -  [R0402_0OHM]  289.51 93.74 180 top
PR700  -  [R_0603]  187.44 178.96 180 top
PR701  -  [R_0201]  188.05 187.6 180 top
PR702  -  [R_1206]  203.63 183.47 90 top
PR703  -  [R_0201]  196.81 186.45 180 top
PR704  -  [R_0402]  188.76 187.22 0 top
PR705  -  [R_0402]  188.72 182.39 180 top
PR706  -  [R_0603]  195.54 183.48 270 top
PR707  -  [R_0402]  190.42 179.65 90 top
PR708  -  [R_0201]  195.63 186.49 270 top
PR709  -  [R_0201]  196.3 185.31 180 top
PR710  -  [R_0201]  192.23 186.45 0 top
PR711  -  [R_0402]  187.38 183.71 90 top
PR712  -  [R_0201]  184.45 186.57 90 top
PR713  -  [R_0201]  184.96 185.82 180 top
PR715  -  [R_0402]  180.19 187.38 0 top
PR717  -  [R0402_0OHM]  184.4 184.35 180 top
PR718  -  [R_0201]  188.14 183.62 90 top
PR800  -  [R_0603]  103.37 128.03 180 bottom
PR801  -  [R_0603]  106.41 126.38 0 top
PR802  -  [R0402_0OHM]  109.14 128.34 90 bottom
PR803  -  [R0402_0OHM]  111.56 131.79 270 bottom
PR804  -  [R_0402]  110.54 130.88 90 bottom
